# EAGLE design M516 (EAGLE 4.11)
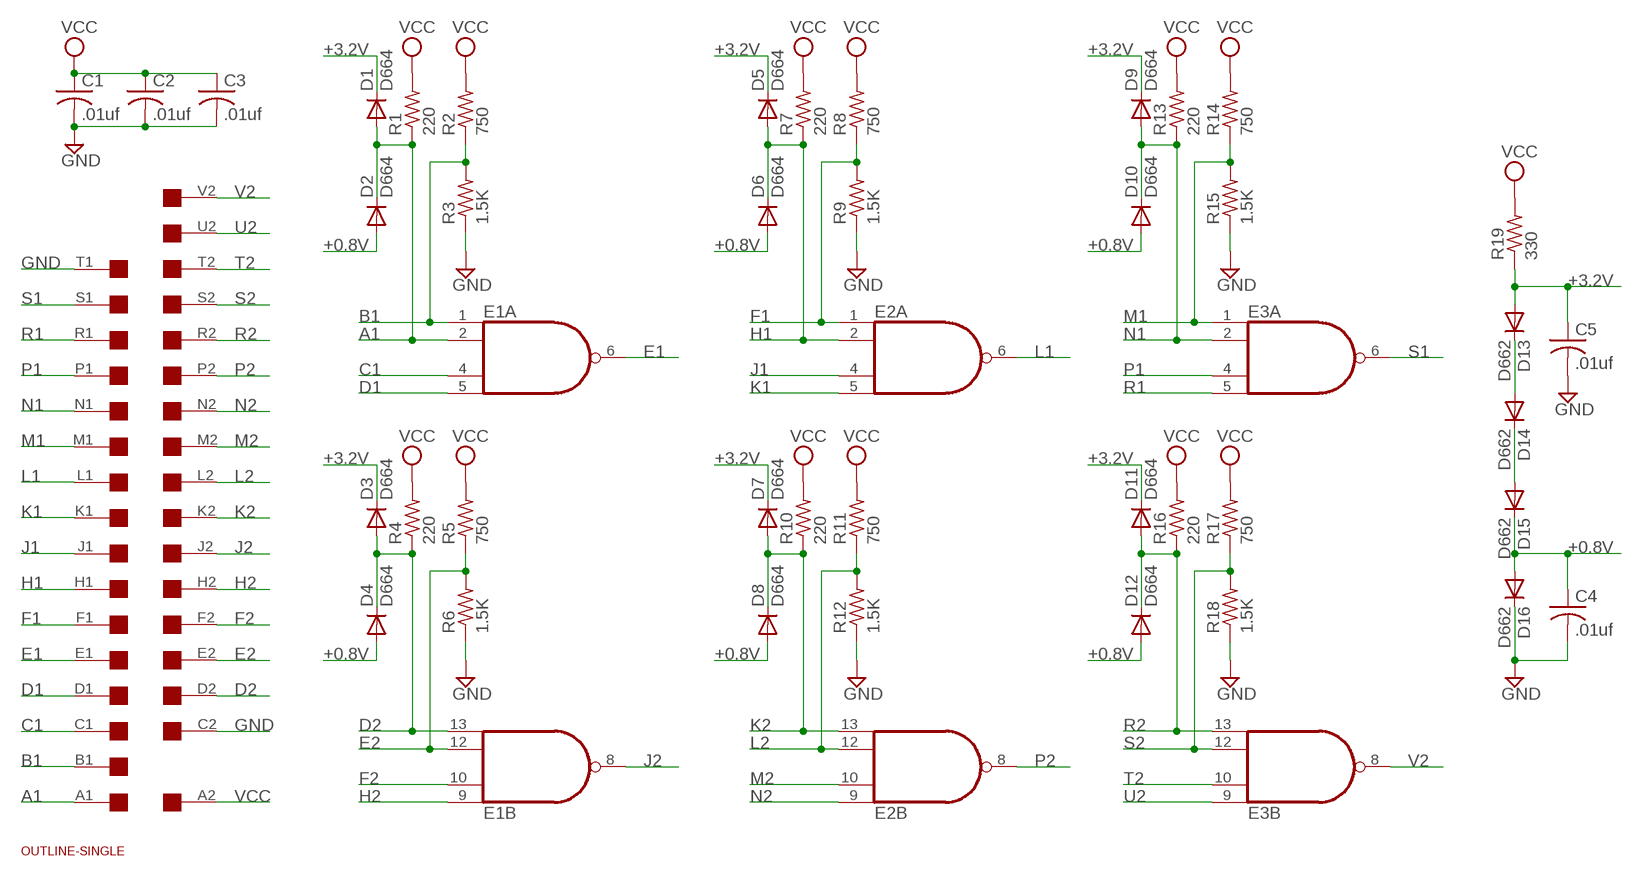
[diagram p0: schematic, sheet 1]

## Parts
C1  .01uf  C-US050-025X075  [C050-025X075]
C2  .01uf  C-US050-025X075  [C050-025X075]
C3  .01uf  C-US050-025X075  [C050-025X075]
C4  .01uf  C-US050-025X075  [C050-025X075]
C5  .01uf  C-US050-025X075  [C050-025X075]
D1  D664  1N4148  [DO35-10]
D2  D664  1N4148  [DO35-10]
D3  D664  1N4148  [DO35-10]
D4  D664  1N4148  [DO35-10]
D5  D664  1N4148  [DO35-10]
D6  D664  1N4148  [DO35-10]
D7  D664  1N4148  [DO35-10]
D8  D664  1N4148  [DO35-10]
D9  D664  1N4148  [DO35-10]
D10  D664  1N4148  [DO35-10]
D11  D664  1N4148  [DO35-10]
D12  D664  1N4148  [DO35-10]
D13  D662  1N4148  [DO35-10]
D14  D662  1N4148  [DO35-10]
D15  D662  1N4148  [DO35-10]
D16  D662  1N4148  [DO35-10]
E1  74S20N  [DIL14]
E2  74S20N  [DIL14]
E3  74S20N  [DIL14]
R1  220  R-US_0207/10  [0207/10]
R2  750  R-US_0207/10  [0207/10]
R3  1.5K  R-US_0207/10  [0207/10]
R4  220  R-US_0207/10  [0207/10]
R5  750  R-US_0207/10  [0207/10]
R6  1.5K  R-US_0207/10  [0207/10]
R7  220  R-US_0207/10  [0207/10]
R8  750  R-US_0207/10  [0207/10]
R9  1.5K  R-US_0207/10  [0207/10]
R10  220  R-US_0207/10  [0207/10]
R11  750  R-US_0207/10  [0207/10]
R12  1.5K  R-US_0207/10  [0207/10]
R13  220  R-US_0207/10  [0207/10]
R14  750  R-US_0207/10  [0207/10]
R15  1.5K  R-US_0207/10  [0207/10]
R16  220  R-US_0207/10  [0207/10]
R17  750  R-US_0207/10  [0207/10]
R18  1.5K  R-US_0207/10  [0207/10]
R19  330  R-US_0207/10  [0207/10]
U$1  OUTLINE-SINGLE  [SINGLE]
U$2  SINGLE  [EDGE-CON2]

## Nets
+0.8V: C4.1 D2.A D4.A D6.A D8.A D10.A D12.A D15.C D16.A
+3.2V: C5.1 D1.C D3.C D5.C D7.C D9.C D11.C D13.A R19.1
A1: D1.A D2.C E1.2(A:I1) R1.1 U$2.A1
B1: E1.1(A:I0) R2.1 R3.2 U$2.B1
C1: E1.4(A:I2) U$2.C1
D1: E1.5(A:I3) U$2.D1
D2: D3.A D4.C E1.13(B:I3) R4.1 U$2.D2
E1: E1.6(A:O) U$2.E1
E2: E1.12(B:I2) R5.1 R6.2 U$2.E2
F1: E2.1(A:I0) R8.1 R9.2 U$2.F1
F2: E1.10(B:I1) U$2.F2
GND [Supply]: C1.2 C2.2 C3.2 C4.2 C5.2 D16.C R3.1 R6.1 R9.1 R12.1 R15.1 R18.1 U$2.C2 U$2.T1
H1: D5.A D6.C E2.2(A:I1) R7.1 U$2.H1
H2: E1.9(B:I0) U$2.H2
J1: E2.4(A:I2) U$2.J1
J2: E1.8(B:O) U$2.J2
K1: E2.5(A:I3) U$2.K1
K2: D7.A D8.C E2.13(B:I3) R10.1 U$2.K2
L1: E2.6(A:O) U$2.L1
L2: E2.12(B:I2) R11.1 R12.2 U$2.L2
M1: E3.1(A:I0) R14.1 R15.2 U$2.M1
M2: E2.10(B:I1) U$2.M2
N1: D9.A D10.C E3.2(A:I1) R13.1 U$2.N1
N2: E2.9(B:I0) U$2.N2
N$49: D13.C D14.A
N$50: D14.C D15.A
P1: E3.4(A:I2) U$2.P1
P2: E2.8(B:O) U$2.P2
R1: E3.5(A:I3) U$2.R1
R2: D11.A D12.C E3.13(B:I3) R16.1 U$2.R2
S1: E3.6(A:O) U$2.S1
S2: E3.12(B:I2) R17.1 R18.2 U$2.S2
T2: E3.10(B:I1) U$2.T2
U2: E3.9(B:I0) U$2.U2
V2: E3.8(B:O) U$2.V2
VCC [Supply]: C1.1 C2.1 C3.1 R1.2 R2.2 R4.2 R5.2 R7.2 R8.2 R10.2 R11.2 R13.2 R14.2 R16.2 R17.2 R19.2 U$2.A2
Unconnected: U$2.B2 U$2.U1 U$2.V1

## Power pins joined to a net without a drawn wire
GND: E1.7(P:GND) E2.7(P:GND) E3.7(P:GND)
VCC: E1.14(P:VCC) E2.14(P:VCC) E3.14(P:VCC)

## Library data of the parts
C1-C5 = rcl:C-US: CAPACITOR, American symbol
D1-D16 = diode:1N4148: DIODE
E1-E3 = 74xx-jameco:74*20: Dual 4-input NAND gate
R1-R19 = rcl:R-US_: RESISTOR, American symbol
U$1 = dec-con:OUTLINE-*: Board outlines for DEC boards.
U$2 = dec-con:SINGLE: Single-Height DEC board

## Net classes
1 Supply: width 0.635 mm

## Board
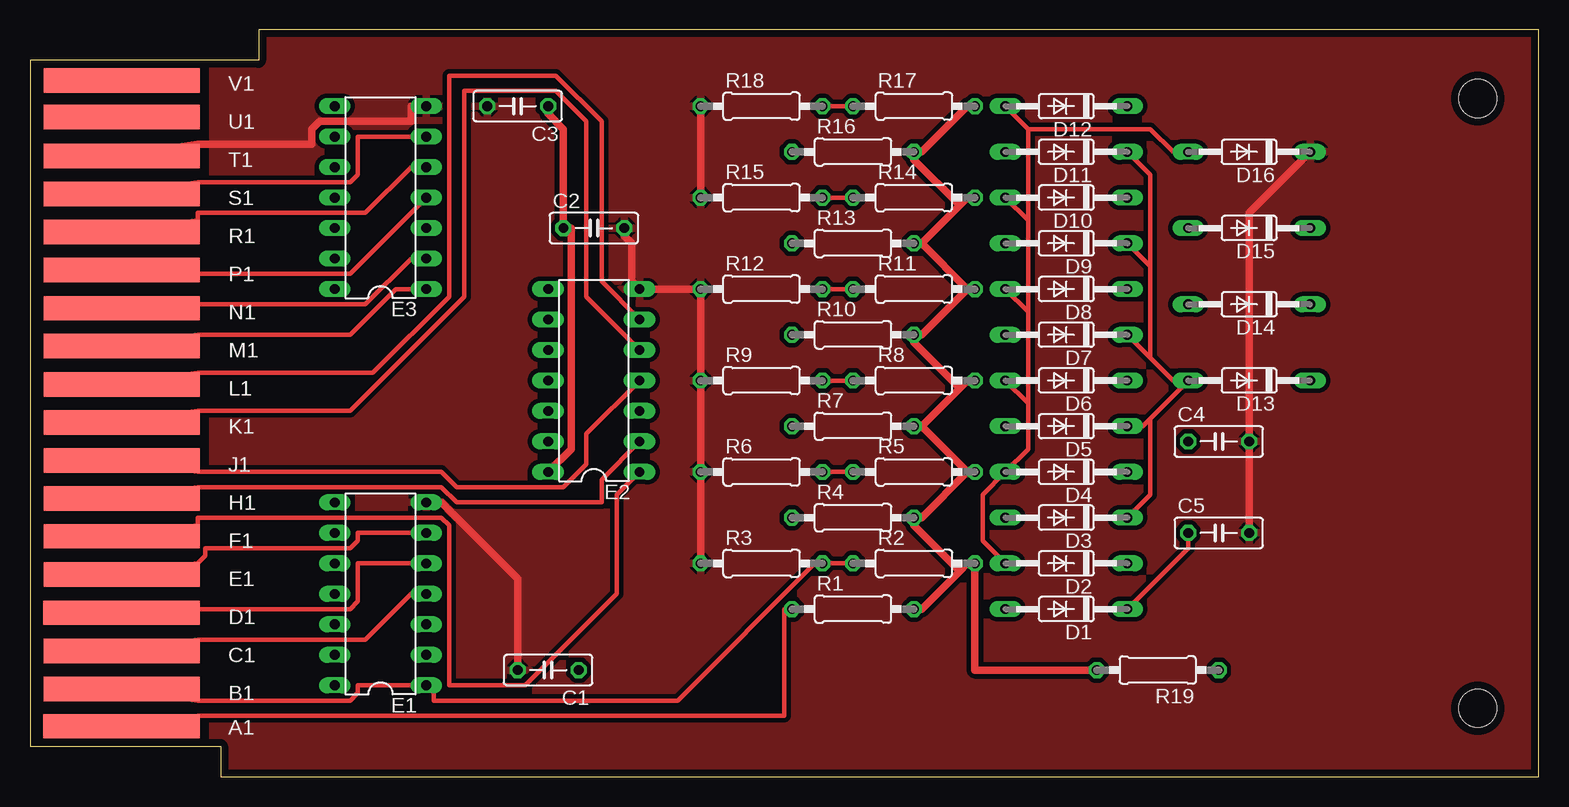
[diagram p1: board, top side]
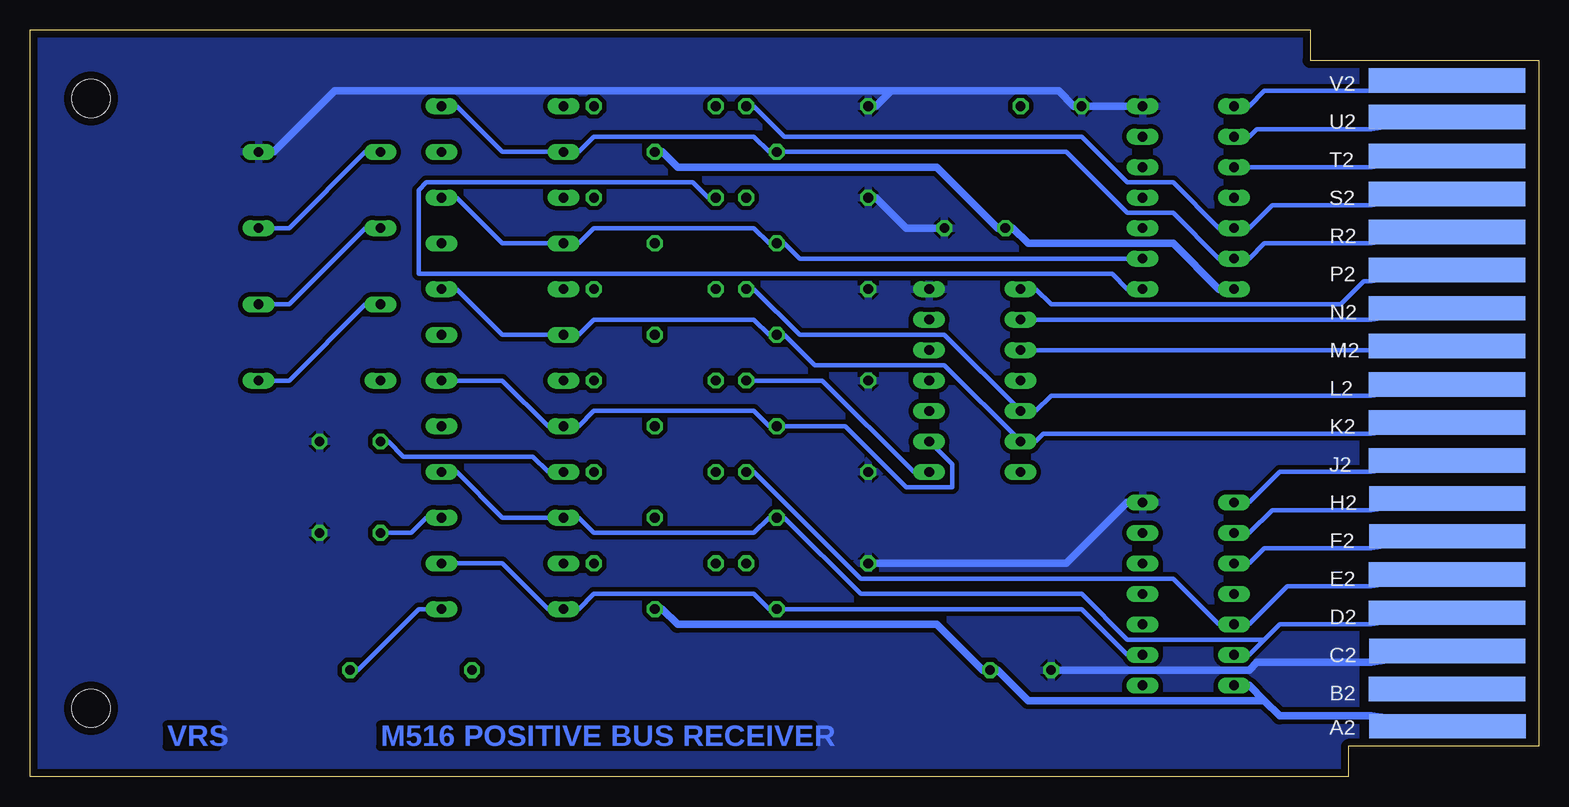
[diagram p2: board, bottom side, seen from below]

Size 125.73 x 62.23 mm. Coordinates in mm from the lower left corner, seen from the top.
Copper layers (1*16): Top 0.035mm / dielectric 1.5mm / Bottom 0.035mm
Design rules "15mils": minimum track width 15mil, minimum drill 24mil, track to track 15mil, track to pad 10mil, pad to pad 10mil, via to via 10mil, smd to smd 10mil, copper to edge 25mil, drill to drill 10mil, minimum pad ring 10mil, minimum via ring 8mil, stop-mask expansion 0mil, vias tented up to drill 0mil, thermal gap 10mil

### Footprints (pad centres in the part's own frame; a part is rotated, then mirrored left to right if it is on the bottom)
C050-025X075 = drill 0.813 octagon: 1 -2.54,0; 2 2.54,0
DO35-10 = drill 0.813 long: A 5.08,0; C -5.08,0
DIL14 = drill 0.813 long: 1 -7.62,-3.81; 2 -5.08,-3.81; 3 -2.54,-3.81; 4 0,-3.81; 5 2.54,-3.81; 6 5.08,-3.81; 7 7.62,-3.81; 8 7.62,3.81; 9 5.08,3.81; 10 2.54,3.81; 11 0,3.81; 12 -2.54,3.81; 13 -5.08,3.81; 14 -7.62,3.81
0207/10 = drill 0.813 octagon: 1 -5.08,0; 2 5.08,0
SINGLE = hole 3.175: 120.65,56.515; 120.65,5.715
EDGE-CON2 = smd 13.017 x 2.032: A1 7.633,4.207; B1 7.639,7.327; C1 7.636,10.489; D1 7.633,13.665; E1 7.642,16.84; F1 7.642,20.041; H1 7.642,23.19; J1 7.642,26.34; K1 7.642,29.515; L1 7.642,32.69; M1 7.642,35.89; N1 7.642,39.04; P1 7.642,42.24; R1 7.642,45.39; S1 7.642,48.565; T1 7.642,51.74; U1 7.642,54.966; V1 7.642,58.026 | smd 13.017 x 2.032 bottom: A2 7.614,4.207; B2 7.642,7.328; C2 7.617,10.49; D2 7.642,13.665; E2 7.642,16.84; F2 7.617,20.041; H2 7.617,23.19; J2 7.642,26.34; K2 7.642,29.515; L2 7.642,32.69; M2 7.642,35.89; N2 7.642,39.04; P2 7.642,42.24; R2 7.642,45.39; S2 7.642,48.565; T2 7.642,51.74; U2 7.642,54.966; V2 7.642,58.026

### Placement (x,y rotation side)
C1  43.18,8.89 180 top
C2  46.99,45.72 0 top
C3  40.64,55.88 180 top
C4  99.06,27.94 0 top
C5  99.06,20.32 0 top
D1  86.36,13.97 180 top
D2  86.36,17.78 180 top
D3  86.36,21.59 180 top
D4  86.36,25.4 180 top
D5  86.36,29.21 180 top
D6  86.36,33.02 180 top
D7  86.36,36.83 180 top
D8  86.36,40.64 180 top
D9  86.36,44.45 180 top
D10  86.36,48.26 180 top
D11  86.36,52.07 180 top
D12  86.36,55.88 180 top
D13  101.6,33.02 180 top
D14  101.6,39.37 180 top
D15  101.6,45.72 180 top
D16  101.6,52.07 180 top
E1  29.21,15.24 90 top
E2  46.99,33.02 90 top
E3  29.21,48.26 90 top
R1  68.58,13.97 0 top
R2  73.66,17.78 0 top
R3  60.96,17.78 0 top
R4  68.58,21.59 0 top
R5  73.66,25.4 0 top
R6  60.96,25.4 0 top
R7  68.58,29.21 0 top
R8  73.66,33.02 0 top
R9  60.96,33.02 0 top
R10  68.58,36.83 0 top
R11  73.66,40.64 0 top
R12  60.96,40.64 0 top
R13  68.58,44.45 0 top
R14  73.66,48.26 0 top
R15  60.96,48.26 0 top
R16  68.58,52.07 0 top
R17  73.66,55.88 0 top
R18  60.96,55.88 0 top
R19  93.98,8.89 180 top
U$1  0,0 0 top
U$2  0,0 0 top

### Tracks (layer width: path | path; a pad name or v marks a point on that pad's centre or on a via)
+0.8V
  Top 0.381: D2.A 79.38,19.68 79.38,23.5 D4.A 83.19,27.3 83.19,31.11 | 83.19,31.11 D6.A | 83.19,31.11 83.19,38.73 | 83.19,38.73 D8.A | 83.19,38.73 83.19,46.35 | 83.19,46.35 D10.A | 83.19,46.35 83.19,53.98 | 83.19,53.98 D12.A | 83.19,53.98 93.35,53.98 95.25,52.07 D16.A
  Bottom 0.381: D16.A 97.79,52.07 104.14,45.72 D15.C | C4.1 95.89,27.94 94.62,26.67 83.82,26.67 82.55,25.4 D4.A
+3.2V
  Top 0.381: D1.C 96.52,19.05 C5.1 | 93.35,29.84 92.71,29.21 D5.C | 93.35,29.84 D13.A 95.25,33.02 93.35,34.92 | 93.35,34.92 D7.C | 93.35,34.92 93.35,42.55 | 93.35,42.55 D9.C | 93.35,42.55 93.35,50.16 D11.C | 93.35,29.84 93.35,23.5 D3.C
  Bottom 0.381: D3.C 92.71,21.59 93.98,20.32 C5.1 | R19.1 98.43,8.89 93.35,13.97 D1.C
A1
  Top 0.381: U$2.A1 13.97,5.08 62.87,5.08 62.87,13.97 R1.1
  Bottom 0.381: D2.C 86.36,17.78 82.55,13.97 D1.A 80.01,13.97 78.74,15.24 65.41,15.24 64.14,13.97 R1.1 38.1,13.97 34.29,10.16 E1.2
B1
  Top 0.381: R2.1 R3.2 65.41,17.78 53.98,6.35 33.66,6.35 33.66,6.99 E1.1 27.31,7.62 27.31,6.99 26.67,6.35 13.97,6.35 U$2.B1
C1
  Top 0.381: E1.4 31.75,15.24 27.94,11.43 13.97,11.43 U$2.C1
D1
  Top 0.381: E1.5 27.31,17.78 27.31,14.61 26.67,13.97 13.97,13.97 U$2.D1
D2
  Bottom 0.381: D4.C 90.17,25.4 86.36,21.59 D3.A 80.01,21.59 78.74,20.32 65.41,20.32 64.14,21.59 R4.1 62.87,21.59 56.52,15.24 38.1,15.24 34.29,11.43 22.86,11.43 | 22.86,11.43 21.59,12.7 13.97,12.7 U$2.D2 | 22.86,11.43 24.13,10.16 E1.13
E1
  Top 0.381: E1.6 27.31,20.32 27.31,19.68 26.67,19.05 14.61,19.05 14.61,18.41 13.97,17.78 U$2.E1
E2
  Top 0.381: R6.2 R5.1
  Bottom 0.381: U$2.E2 13.97,15.88 20.96,15.88 24.13,12.7 E1.12 26.67,12.7 30.48,16.51 56.52,16.51 65.41,25.4 R6.2
F1
  Top 0.381: R9.2 R8.1 | E2.1 48.9,23.5 48.9,15.24 41.28,7.62 34.93,7.62 34.93,20.95 34.29,21.59 13.97,21.59 13.97,20.95 U$2.F1
  Bottom 0.381: E2.1 52.07,25.4 59.69,33.02 R9.2
F2
  Bottom 0.381: E1.10 24.13,17.78 22.86,19.05 13.97,19.05 U$2.F2
GND
  Top 0.635: C5.2 C4.2 101.6,46.99 D16.C | E1.7 34.29,22.86 40.64,16.51 C1.2 | R3.1 R6.1 R9.1 R12.1 E2.7 50.17,41.27 50.17,44.45 49.53,45.09 C2.2 | R15.1 R18.1 | U$2.T1 13.97,52.7 23.5,52.7 23.5,53.98 24.13,54.61 31.75,54.61 31.75,55.88 E3.7
  Bottom 0.635: E3.7 C3.2 38.74,55.88 40.01,57.15 53.98,57.15 | R15.1 55.25,48.26 52.71,45.72 C2.2 | 53.98,57.15 55.25,55.88 R18.1 | E1.7 34.29,22.86 39.37,17.78 R3.1 | U$2.C2 13.97,9.53 23.5,9.53 24.13,8.89 C1.2 | 53.98,57.15 100.33,57.15 105.41,52.07 D16.C
  pour Top: 16.51,0 125.73,0 125.73,62.23 15.24,62.23 15.24,0
  pour Bottom: 16.51,0 125.73,0 125.73,62.23 15.24,62.23 15.24,0
H1
  Top 0.381: U$2.H1 13.97,24.13 34.29,24.13 35.56,22.86 47.63,22.86 47.63,24.77 E2.2
  Bottom 0.381: D6.C 86.36,33.02 82.55,29.21 D5.A 80.01,29.21 78.74,30.48 65.41,30.48 64.14,29.21 R7.1 57.79,29.21 52.71,24.13 48.9,24.13 48.9,26.04 E2.2
H2
  Bottom 0.381: E1.9 24.13,20.32 22.23,22.23 13.97,22.23 U$2.H2
J1
  Top 0.381: E2.4 46.36,28.57 46.36,26.04 44.45,24.13 35.56,24.13 34.29,25.4 13.97,25.4 U$2.J1
J2
  Bottom 0.381: E1.8 24.13,22.86 21.59,25.4 13.97,25.4 U$2.J2
K1
  Top 0.381: E2.5 46.36,40.01 46.36,54.61 43.82,57.15 36.2,57.15 36.2,40.01 26.67,30.48 13.97,30.48 U$2.K1
K2
  Bottom 0.381: D8.C 90.17,40.64 86.36,36.83 D7.A 80.01,36.83 78.74,38.1 65.41,38.1 64.14,36.83 R10.1 62.87,36.83 60.33,34.29 49.53,34.29 E2.13 41.91,27.94 41.28,28.57 13.97,28.57 U$2.K2
L1
  Top 0.381: E2.6 47.63,41.27 47.63,54.61 43.82,58.42 34.93,58.42 34.93,40.01 28.58,33.66 13.97,33.66 U$2.L1
L2
  Top 0.381: R12.2 R11.1
  Bottom 0.381: U$2.L2 13.97,31.75 40.64,31.75 41.91,30.48 E2.12 49.53,36.83 61.6,36.83 65.41,40.64 R12.2
M1
  Top 0.381: R14.1 R15.2 | E3.1 30.48,40.64 26.67,36.83 13.97,36.83 U$2.M1
  Bottom 0.381: R14.1 69.22,48.26 70.49,49.53 92.71,49.53 93.35,48.9 93.35,41.91 35.56,41.91 34.29,40.64 E3.1
M2
  Bottom 0.381: E2.10 13.97,35.56 U$2.M2
N1
  Top 0.381: E3.2 31.75,43.18 27.94,39.37 13.97,39.37 U$2.N1
  Bottom 0.381: D10.C 90.17,48.26 86.36,44.45 D9.A 80.01,44.45 78.74,45.72 65.41,45.72 64.14,44.45 R13.1 62.87,44.45 61.6,43.18 E3.2
N2
  Bottom 0.381: E2.9 13.97,38.1 U$2.N2
N$49
  Bottom 0.381: D14.A 97.79,39.37 104.14,33.02 D13.C
N$50
  Bottom 0.381: D15.A 97.79,45.72 104.14,39.37 D14.C
P1
  Top 0.381: E3.4 26.67,41.91 13.97,41.91 U$2.P1
P2
  Bottom 0.381: E2.8 41.91,40.64 40.64,39.37 16.51,39.37 14.61,41.27 13.97,41.27 U$2.P2
R1
  Top 0.381: E3.5 31.75,50.8 27.94,46.99 13.97,46.99 13.97,46.35 U$2.R1
R2
  Bottom 0.381: D12.C 90.17,55.88 86.36,52.07 D11.A 80.01,52.07 78.74,53.34 65.41,53.34 64.14,52.07 R16.1 39.37,52.07 34.29,46.99 30.48,46.99 26.67,43.18 E3.13 24.13,43.18 22.86,44.45 13.97,44.45 U$2.R2
S1
  Top 0.381: E3.6 27.31,53.34 27.31,50.16 26.67,49.53 13.97,49.53 U$2.S1
S2
  Top 0.381: R18.2 R17.1
  Bottom 0.381: U$2.S2 13.97,47.62 22.23,47.62 24.13,45.72 E3.12 26.67,45.72 30.48,49.53 34.29,49.53 38.1,53.34 62.87,53.34 65.41,55.88 R18.2
T2
  Bottom 0.381: E3.10 13.97,50.8 U$2.T2
U2
  Bottom 0.381: E3.9 24.13,53.34 23.5,53.98 13.97,53.98 U$2.U2
V2
  Bottom 0.381: E3.8 24.13,55.88 22.86,57.15 13.97,57.15 U$2.V2
VCC
  Top 0.635: E2.14 45.09,27.3 45.09,45.72 C2.1 44.45,53.98 43.18,55.24 C3.1 | 77.47,47.62 78.11,48.26 R14.2 | 74.3,44.45 77.47,47.62 | 77.47,47.62 73.66,51.44 R16.2 74.3,52.07 78.11,55.88 R17.2 | 78.11,40.64 74.3,44.45 | 74.3,44.45 R13.2 | 77.47,32.38 78.11,33.02 R8.2 | 74.3,29.21 77.47,32.38 | 77.47,32.38 73.66,36.2 R10.2 74.3,36.83 78.11,40.64 | 78.11,25.4 74.3,29.21 | 74.3,29.21 R7.2 | 77.47,17.14 78.11,17.78 R2.2 78.74,8.89 R19.2 | 77.47,17.14 74.3,13.97 R1.2 | 77.47,17.14 73.66,20.95 R4.2 74.3,21.59 78.11,25.4 | 78.11,25.4 R5.2 | 78.11,40.64 R11.2
  Bottom 0.635: 22.86,6.35 21.59,5.08 13.97,5.08 U$2.A2 | 22.86,6.35 24.13,7.62 E1.14 | 22.86,6.35 42.55,6.35 45.09,8.89 C1.1 46.36,8.89 50.17,12.7 71.76,12.7 73.03,13.97 R1.2 | E3.14 26.67,40.64 30.48,44.45 42.55,44.45 43.82,45.72 C2.1 45.09,45.72 50.17,50.8 71.76,50.8 73.03,52.07 R16.2

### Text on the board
Bottom: M516 POSITIVE BUS RECEIVER | VRS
